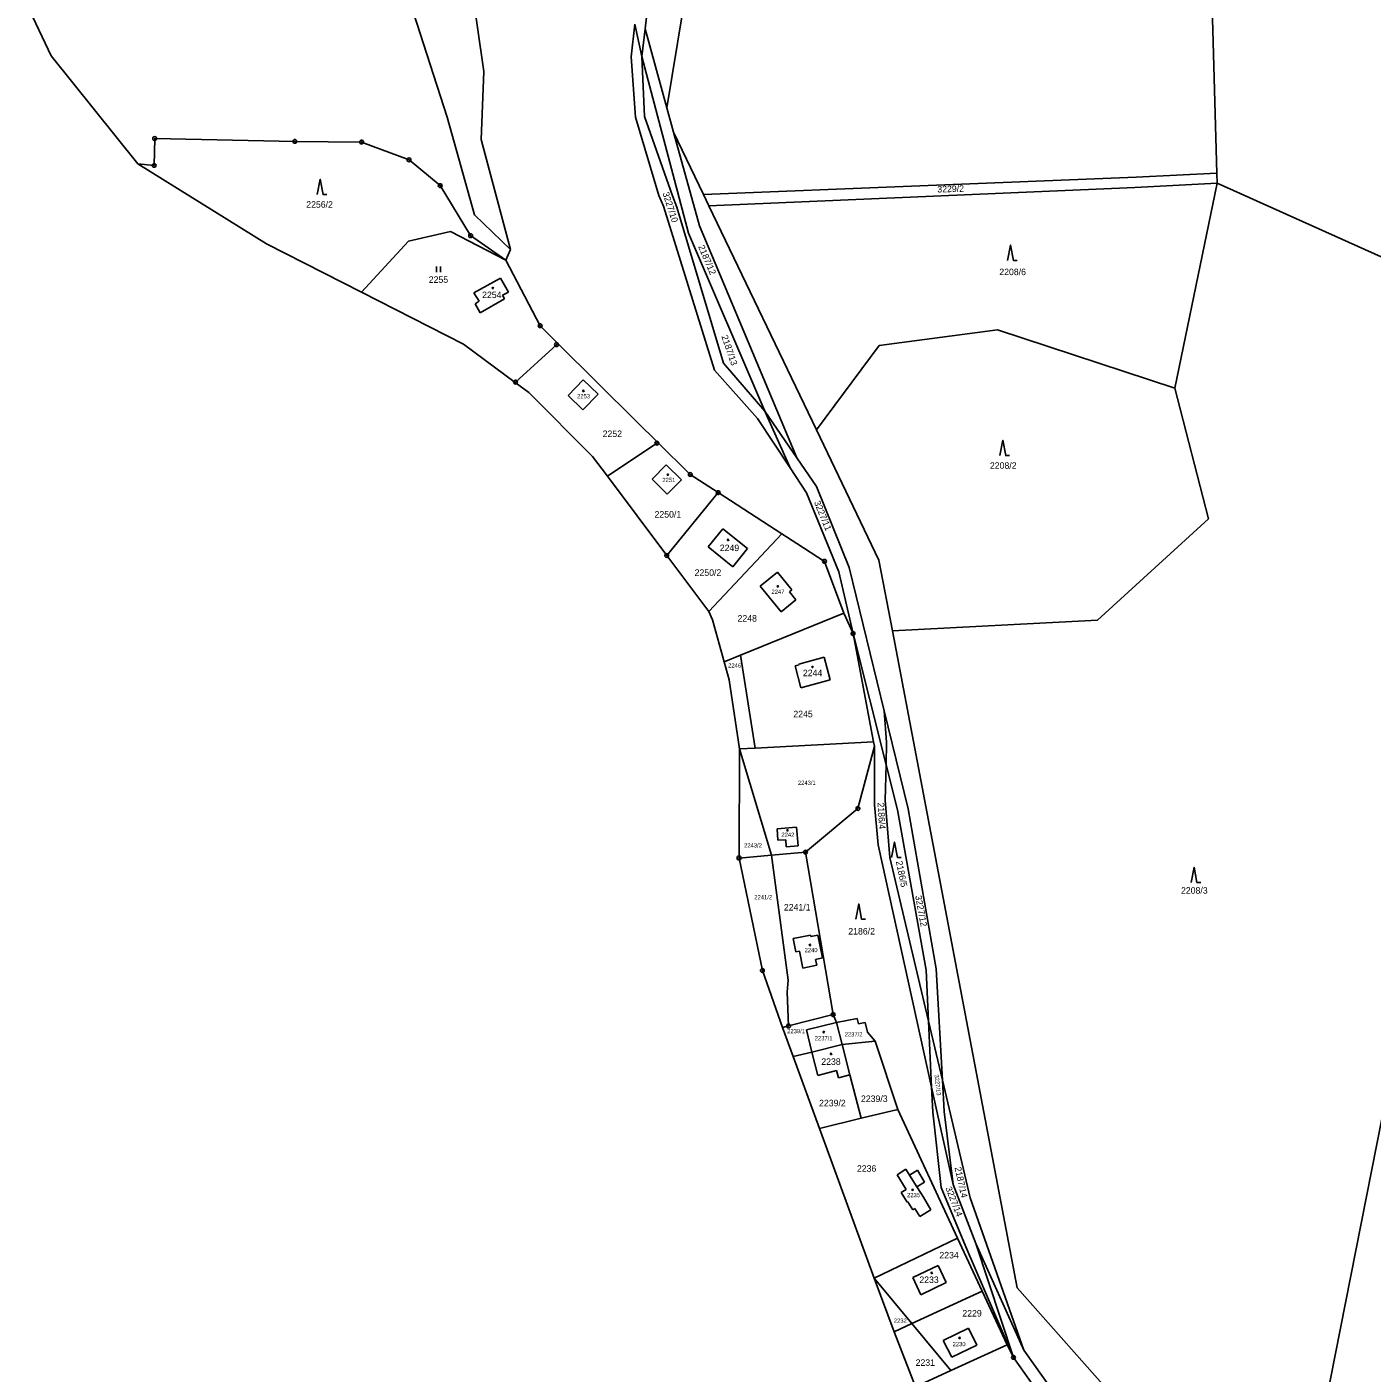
# Model space of a CAD drawing. Extents: x -736345 to -729997, y -1130177 to -1122501.
# Drawn here: x -734700.4 to -734349.4, y -1129772.2 to -1129421.1 of the extents above; entities that cross this region are included whole.
import ezdxf

# ---------------------------------------------------------------- set-up
doc = ezdxf.new("R2010")
doc.units = 0
for name, color, linetype in [('Vrstva 1', 7, 'Continuous'), ('Vrstva 13', 7, 'Continuous'), ('Vrstva 18', 7, 'Continuous'), ('Vrstva 19', 7, 'Continuous'), ('Vrstva 25', 7, 'Continuous'), ('Vrstva 4', 7, 'Continuous')]:
    doc.layers.add(name, color=color, linetype=linetype)

msp = doc.modelspace()

# ---------------------------------------------------------------- linework, layer by layer
at = {"layer": 'Vrstva 1'}
for points in [[(-734533.42, -1129442.26), (-734522.14, -1129373.62)], [(-734612.83, -1129376.15), (-734590.74, -1129444.65)], [(-734391.5, -1129403.36), (-734389.91, -1129459.3)], [(-734584.52, -1129409.15), (-734581.13, -1129432.75)], [(-734539.12, -1129421.6), (-734537.7, -1129409.35)], [(-734541.75, -1129420.42), (-734542.71, -1129428.92)], [(-734541.75, -1129420.42), (-734539.95, -1129428.83)], [(-734539.95, -1129428.83), (-734539.12, -1129421.6)], [(-734533.42, -1129442.26), (-734539.12, -1129421.6)], [(-734541.63, -1129444.65), (-734542.71, -1129428.92)], [(-734539.24, -1129444.51), (-734539.95, -1129428.83)], [(-734539.95, -1129428.83), (-734527.75, -1129474.96)], [(-734581.13, -1129432.75), (-734581.87, -1129450.52)], [(-734531.67, -1129448.59), (-734533.42, -1129442.26)], [(-734590.74, -1129444.65), (-734583.63, -1129470.11)], [(-734535.48, -1129465.07), (-734541.63, -1129444.65)], [(-734531.93, -1129465.17), (-734539.24, -1129444.51)], [(-734667.17, -1129457.25), (-734667.04, -1129450.26)], [(-734630.47, -1129451), (-734667.04, -1129450.26)], [(-734581.87, -1129450.52), (-734574.23, -1129479.22)], [(-734523.87, -1129464.85), (-734531.67, -1129448.59)], [(-734524.93, -1129473.03), (-734531.67, -1129448.59)], [(-734630.47, -1129451), (-734613.06, -1129451.16)], [(-734600.69, -1129455.81), (-734613.06, -1129451.16)], [(-734671.43, -1129456.81), (-734667.17, -1129457.25)], [(-734592.57, -1129462.53), (-734600.69, -1129455.81)], [(-734523.87, -1129464.85), (-734411.02, -1129460.3)], [(-734389.91, -1129459.3), (-734411.02, -1129460.3)], [(-734389.91, -1129459.3), (-734389.83, -1129461.93)], [(-734584.62, -1129475.58), (-734592.57, -1129462.53)], [(-734522.44, -1129467.82), (-734523.87, -1129464.85)], [(-734411.35, -1129462.99), (-734522.44, -1129467.82)], [(-734389.83, -1129461.93), (-734411.35, -1129462.99)], [(-734400.92, -1129515.32), (-734389.83, -1129461.93)], [(-734347.07, -1129481.06), (-734389.83, -1129461.93)], [(-734534.34, -1129467.87), (-734535.48, -1129465.07)], [(-734534.34, -1129467.87), (-734520.97, -1129510.65)], [(-734530.86, -1129468.19), (-734531.93, -1129465.17)], [(-734518.69, -1129508.85), (-734530.86, -1129468.19)], [(-734522.44, -1129467.82), (-734494.4, -1129526.24)], [(-734583.63, -1129470.11), (-734574.23, -1129479.22)], [(-734589.91, -1129474.48), (-734600.81, -1129477.05)], [(-734575.47, -1129481.98), (-734589.91, -1129474.48)], [(-734507.88, -1129521.35), (-734527.75, -1129474.96)], [(-734524.93, -1129473.03), (-734499.53, -1129533.55)], [(-734600.81, -1129477.05), (-734613.09, -1129490.3)], [(-734575.47, -1129481.98), (-734584.62, -1129475.58)], [(-734574.23, -1129479.22), (-734575.47, -1129481.98)], [(-734566.49, -1129499.07), (-734575.47, -1129481.98)], [(-734576.81, -1129486.63), (-734583.74, -1129490.47)], [(-734574.77, -1129490.31), (-734576.81, -1129486.63)], [(-734583.74, -1129490.47), (-734582.41, -1129492.69)], [(-734582.41, -1129492.69), (-734583.46, -1129493.32)], [(-734582.11, -1129495.68), (-734575.75, -1129492.05)], [(-734576.27, -1129491.14), (-734574.77, -1129490.31)], [(-734575.75, -1129492.05), (-734576.27, -1129491.14)], [(-734583.46, -1129493.32), (-734582.11, -1129495.68)], [(-734561.9, -1129503.74), (-734566.49, -1129499.07)], [(-734478.05, -1129504.24), (-734447.18, -1129500.1)], [(-734447.18, -1129500.1), (-734400.92, -1129515.32)], [(-734572.9, -1129513.77), (-734562.2, -1129504.01)], [(-734562.2, -1129504.01), (-734561.9, -1129503.74)], [(-734561.9, -1129503.74), (-734541.38, -1129524.04)], [(-734494.4, -1129526.24), (-734478.05, -1129504.24)], [(-734520.97, -1129510.65), (-734509.77, -1129523.24)], [(-734507.88, -1129521.35), (-734518.69, -1129508.85)], [(-734572.97, -1129513.84), (-734572.9, -1129513.77)], [(-734559.21, -1129517.26), (-734555.23, -1129513.14)], [(-734555.23, -1129513.14), (-734551.33, -1129516.91)], [(-734555.31, -1129521.03), (-734559.21, -1129517.26)], [(-734551.33, -1129516.91), (-734555.31, -1129521.03)], [(-734400.92, -1129515.32), (-734392.09, -1129549.47)], [(-734541.38, -1129524.04), (-734535.77, -1129529.55)], [(-734509.77, -1129523.24), (-734501.3, -1129536.1)], [(-734499.53, -1129533.55), (-734507.88, -1129521.35)], [(-734507.88, -1129521.35), (-734501.3, -1129536.1)], [(-734478.09, -1129560.23), (-734494.4, -1129526.24)], [(-734536.02, -1129529.71), (-734548.95, -1129538.34)], [(-734535.77, -1129529.55), (-734536.02, -1129529.71)], [(-734535.77, -1129529.55), (-734527.31, -1129537.87)], [(-734494.41, -1129541.04), (-734499.53, -1129533.55)], [(-734537.28, -1129539.05), (-734533.58, -1129535.32)], [(-734533.58, -1129535.32), (-734529.63, -1129539.24)], [(-734527.31, -1129537.87), (-734520.04, -1129542.59)], [(-734501.3, -1129536.1), (-734496.97, -1129542.68)], [(-734533.33, -1129542.97), (-734537.28, -1129539.05)], [(-734529.63, -1129539.24), (-734533.33, -1129542.97)], [(-734485.86, -1129562.13), (-734494.41, -1129541.04)], [(-734520.04, -1129542.59), (-734533.46, -1129558.99)], [(-734520.04, -1129542.59), (-734503.47, -1129553.35)], [(-734496.97, -1129542.68), (-734488.58, -1129563.27)], [(-734522.65, -1129556.76), (-734518.83, -1129552.03)], [(-734518.83, -1129552.03), (-734512.41, -1129557.21)], [(-734392.09, -1129549.47), (-734421.07, -1129575.85)], [(-734522.5, -1129573.6), (-734503.47, -1129553.35)], [(-734503.47, -1129553.35), (-734499.55, -1129555.9)], [(-734499.55, -1129555.9), (-734492.3, -1129560.52)], [(-734522.65, -1129556.76), (-734516.23, -1129561.94)], [(-734512.41, -1129557.21), (-734516.23, -1129561.94)], [(-734492.3, -1129560.52), (-734487.22, -1129574.06)], [(-734488.58, -1129563.27), (-734484.86, -1129579.37)], [(-734476.74, -1129599.5), (-734485.86, -1129562.13)], [(-734474.6, -1129578.6), (-734478.09, -1129560.23)], [(-734509.07, -1129566.98), (-734504.6, -1129563.35)], [(-734504.6, -1129563.35), (-734500.84, -1129567.95)], [(-734503.59, -1129573.7), (-734509.07, -1129566.98)], [(-734500.84, -1129567.95), (-734501.47, -1129568.46)], [(-734501.47, -1129568.46), (-734499.75, -1129570.57)], [(-734499.75, -1129570.57), (-734503.59, -1129573.7)], [(-734487.22, -1129574.06), (-734514.19, -1129585.02)], [(-734487.22, -1129574.06), (-734484.86, -1129579.37)], [(-734421.07, -1129575.85), (-734474.6, -1129578.6)], [(-734476.25, -1129613.58), (-734484.86, -1129579.37)], [(-734484.86, -1129579.37), (-734479.52, -1129607.57)], [(-734474.6, -1129578.6), (-734442, -1129750)], [(-734514.19, -1129585.02), (-734518.45, -1129586.75)], [(-734514.19, -1129585.02), (-734510.39, -1129609.22)], [(-734499.94, -1129587.76), (-734498.92, -1129587.5)], [(-734498.44, -1129593.52), (-734499.94, -1129587.76)], [(-734498.97, -1129587.3), (-734492.35, -1129585.54)], [(-734498.92, -1129587.5), (-734498.97, -1129587.3)], [(-734492.35, -1129585.54), (-734490.79, -1129591.44)], [(-734490.79, -1129591.44), (-734498.44, -1129593.52)], [(-734470.49, -1129625.11), (-734476.74, -1129599.5)], [(-734476.09, -1129607.64), (-734476.74, -1129599.5)], [(-734479.52, -1129607.57), (-734510.39, -1129609.22)], [(-734479.29, -1129608.68), (-734483.57, -1129624.97)], [(-734479.52, -1129607.57), (-734479.29, -1129608.68)], [(-734479.29, -1129608.68), (-734479.22, -1129624.06)], [(-734476.25, -1129613.58), (-734476.09, -1129607.64)], [(-734510.39, -1129609.22), (-734514.48, -1129609.44)], [(-734506.13, -1129637.15), (-734514.48, -1129609.44)], [(-734476.49, -1129622.79), (-734476.25, -1129613.58)], [(-734473.3, -1129625.29), (-734476.25, -1129613.58)], [(-734475.27, -1129637.79), (-734476.49, -1129622.79)], [(-734483.57, -1129624.97), (-734497.25, -1129636.38)], [(-734479.22, -1129624.06), (-734478.28, -1129634.46)], [(-734465.79, -1129667.18), (-734473.3, -1129625.29)], [(-734463.13, -1129666.77), (-734470.49, -1129625.11)], [(-734504.66, -1129630.28), (-734499.63, -1129629.84)], [(-734499.63, -1129629.84), (-734499.21, -1129634.71)], [(-734504.47, -1129633.28), (-734504.66, -1129630.28)], [(-734502.42, -1129633.13), (-734504.47, -1129633.28)], [(-734502.29, -1129634.94), (-734502.42, -1129633.13)], [(-734506.13, -1129637.15), (-734497.25, -1129636.38)], [(-734499.21, -1129634.71), (-734502.29, -1129634.94)], [(-734497.25, -1129636.38), (-734490.06, -1129678.74)], [(-734478.28, -1129634.46), (-734464.37, -1129697.63)], [(-734514.6, -1129637.89), (-734506.13, -1129637.15)], [(-734506.13, -1129637.15), (-734501.77, -1129669.78)], [(-734465.17, -1129680.47), (-734475.27, -1129637.79)], [(-734333.35, -1129637.24), (-734367.13, -1129808.5)], [(-734500.44, -1129658.9), (-734495.91, -1129657.99)], [(-734495.91, -1129657.99), (-734495.83, -1129658.36)], [(-734495.83, -1129658.36), (-734494.04, -1129658)], [(-734494.04, -1129658), (-734492.84, -1129663.96)], [(-734499.74, -1129662.35), (-734500.44, -1129658.9)], [(-734498.84, -1129662.17), (-734499.74, -1129662.35)], [(-734497.94, -1129666.6), (-734498.84, -1129662.17)], [(-734492.84, -1129663.96), (-734494.62, -1129664.32)], [(-734494.62, -1129664.32), (-734494.3, -1129665.87)], [(-734494.3, -1129665.87), (-734497.94, -1129666.6)], [(-734465.17, -1129680.47), (-734465.79, -1129667.18)], [(-734461.54, -1129695.79), (-734463.13, -1129666.77)], [(-734501.77, -1129669.78), (-734502.06, -1129672.85)], [(-734502.06, -1129672.85), (-734501.66, -1129681.7)], [(-734490.06, -1129678.74), (-734501.66, -1129681.7)], [(-734490.06, -1129678.74), (-734489.19, -1129680.8)], [(-734501.66, -1129681.7), (-734503.24, -1129682.08)], [(-734496.99, -1129682.7), (-734489.19, -1129680.8)], [(-734483.74, -1129679.76), (-734489.19, -1129680.8)], [(-734489.19, -1129680.8), (-734487.72, -1129686.56)], [(-734483.43, -1129681.17), (-734483.74, -1129679.76)], [(-734481.67, -1129680.78), (-734483.43, -1129681.17)], [(-734481.07, -1129683.32), (-734481.67, -1129680.78)], [(-734464.37, -1129697.63), (-734465.17, -1129680.47)], [(-734461.54, -1129695.79), (-734465.17, -1129680.47)], [(-734495.57, -1129688.49), (-734496.99, -1129682.7)], [(-734487.72, -1129686.56), (-734479.06, -1129685.69)], [(-734479.06, -1129685.69), (-734481.07, -1129683.32)], [(-734479.06, -1129685.69), (-734473.2, -1129703.49)], [(-734500.46, -1129689.68), (-734495.57, -1129688.49)], [(-734495.57, -1129688.49), (-734487.72, -1129686.56)], [(-734494.08, -1129694.62), (-734495.57, -1129688.49)], [(-734487.72, -1129686.56), (-734485.7, -1129694.48)], [(-734489.15, -1129693.32), (-734494.08, -1129694.62)], [(-734488.64, -1129695.25), (-734489.15, -1129693.32)], [(-734485.7, -1129694.48), (-734488.64, -1129695.25)], [(-734482.73, -1129705.78), (-734485.7, -1129694.48)], [(-734461.09, -1129704.04), (-734461.54, -1129695.79)], [(-734454.27, -1129726.51), (-734461.54, -1129695.79)], [(-734464.37, -1129697.63), (-734464.06, -1129704.17)], [(-734464.37, -1129697.63), (-734458.77, -1129723.04)], [(-734473.2, -1129703.49), (-734482.73, -1129705.78)], [(-734473.2, -1129703.49), (-734457.62, -1129737.04)], [(-734482.73, -1129705.78), (-734493.61, -1129708.4)], [(-734464.06, -1129704.17), (-734461.89, -1129723.85)], [(-734458.77, -1129723.04), (-734461.09, -1129704.04)], [(-734473.36, -1129720.52), (-734471.06, -1129719.08)], [(-734471, -1129724.33), (-734473.36, -1129720.52)], [(-734471.06, -1129719.08), (-734470.09, -1129720.58)], [(-734468.06, -1129719.34), (-734470.09, -1129720.58)], [(-734468.06, -1129719.34), (-734466.19, -1129722.4)], [(-734472.3, -1129725.14), (-734471, -1129724.33)], [(-734466.19, -1129722.4), (-734468.22, -1129723.64)], [(-734468.22, -1129723.64), (-734466.49, -1129726.36)], [(-734461.89, -1129723.85), (-734455.41, -1129739.28)], [(-734452.86, -1129738.39), (-734458.77, -1129723.04)], [(-734470.73, -1129727.67), (-734472.3, -1129725.14)], [(-734470.52, -1129727.54), (-734470.73, -1129727.67)], [(-734469.24, -1129729.61), (-734470.52, -1129727.54)], [(-734466.49, -1129726.36), (-734464.59, -1129729.68)], [(-734440.32, -1129766.22), (-734454.27, -1129726.51)], [(-734468.74, -1129729.3), (-734469.24, -1129729.61)], [(-734467.45, -1129731.4), (-734468.74, -1129729.3)], [(-734464.59, -1129729.68), (-734467.45, -1129731.4)], [(-734457.62, -1129737.04), (-734479.31, -1129747.47)], [(-734457.62, -1129737.04), (-734451.15, -1129750.87)], [(-734440.32, -1129766.22), (-734452.86, -1129738.39)], [(-734443.01, -1129768.14), (-734452.86, -1129738.39)], [(-734455.41, -1129739.28), (-734443.01, -1129768.14)], [(-734469.3, -1129747.34), (-734462.68, -1129744.17)], [(-734462.68, -1129744.17), (-734460.54, -1129748.63)], [(-734469.49, -1129759.33), (-734479.31, -1129747.47)], [(-734467.16, -1129751.8), (-734469.3, -1129747.34)], [(-734460.54, -1129748.63), (-734467.16, -1129751.8)], [(-734469.49, -1129759.33), (-734451.15, -1129750.87)], [(-734451.15, -1129750.87), (-734444.66, -1129764.85)], [(-734442, -1129750), (-734389.31, -1129809.44)], [(-734474.15, -1129761.48), (-734469.49, -1129759.33)], [(-734469.49, -1129759.33), (-734459.37, -1129771.56)], [(-734461.31, -1129763.69), (-734454.71, -1129760.48)], [(-734454.71, -1129760.48), (-734452.55, -1129764.92)], [(-734459.11, -1129768.06), (-734461.31, -1129763.69)], [(-734444.66, -1129764.85), (-734459.37, -1129771.56)], [(-734452.55, -1129764.92), (-734459.11, -1129768.06)], [(-734443.01, -1129768.14), (-734444.66, -1129764.85)], [(-734432.84, -1129776.73), (-734440.32, -1129766.22)], [(-734443.01, -1129768.14), (-734435.57, -1129778.59)], [(-734459.37, -1129771.56), (-734468.6, -1129775.77)]]:
    msp.add_lwpolyline(points, dxfattribs=at)
at = {"layer": 'Vrstva 13'}
for points in [[(-734700.37, -1129415.29), (-734694.01, -1129428.71)], [(-734694.01, -1129428.71), (-734671.43, -1129456.81)], [(-734671.43, -1129456.81), (-734637.84, -1129477.74)], [(-734613.09, -1129490.3), (-734637.84, -1129477.74)], [(-734613.09, -1129490.3), (-734586.51, -1129503.85)], [(-734586.51, -1129503.85), (-734572.97, -1129513.84)], [(-734572.97, -1129513.84), (-734569.43, -1129516.46)], [(-734552.8, -1129533.21), (-734569.43, -1129516.46)], [(-734548.95, -1129538.34), (-734552.8, -1129533.21)], [(-734548.95, -1129538.34), (-734533.46, -1129558.99)], [(-734533.46, -1129558.99), (-734522.5, -1129573.6)], [(-734521.51, -1129575.8), (-734522.5, -1129573.6)], [(-734518.45, -1129586.75), (-734521.51, -1129575.8)], [(-734517.15, -1129591.4), (-734518.45, -1129586.75)], [(-734514.48, -1129609.44), (-734517.15, -1129591.4)], [(-734514.6, -1129637.89), (-734514.48, -1129609.44)], [(-734508.51, -1129667.22), (-734514.6, -1129637.89)], [(-734503.24, -1129682.08), (-734508.51, -1129667.22)], [(-734500.46, -1129689.68), (-734503.24, -1129682.08)], [(-734493.61, -1129708.4), (-734500.46, -1129689.68)], [(-734479.31, -1129747.47), (-734493.61, -1129708.4)], [(-734479.31, -1129747.47), (-734474.15, -1129761.48)], [(-734468.6, -1129775.77), (-734474.15, -1129761.48)]]:
    msp.add_lwpolyline(points, dxfattribs=at)
at = {"layer": 'Vrstva 25'}
for points in [[(-734624.61, -1129464.88), (-734623.86, -1129460.88), (-734623.11, -1129464.88), (-734622.11, -1129464.88)], [(-734444.52, -1129482.04), (-734443.77, -1129478.04), (-734443.02, -1129482.04), (-734442.02, -1129482.04)], [(-734593.537, -1129485.125), (-734593.537, -1129483.625)], [(-734592.503, -1129485.125), (-734592.503, -1129483.625)], [(-734446.52, -1129532.92), (-734445.77, -1129528.92), (-734445.02, -1129532.92), (-734444.02, -1129532.92)], [(-734474.79, -1129637.75), (-734474.04, -1129633.75), (-734473.29, -1129637.75), (-734472.29, -1129637.75)], [(-734396.65, -1129644.29), (-734395.9, -1129640.29), (-734395.15, -1129644.29), (-734394.15, -1129644.29)], [(-734484.12, -1129653.88), (-734483.37, -1129649.88), (-734482.62, -1129653.88), (-734481.62, -1129653.88)]]:
    msp.add_lwpolyline(points, dxfattribs=at)
for centre, radius in [((-734667.04, -1129450.26), 0.5), ((-734667.04, -1129450.26), 0.032), ((-734630.47, -1129451), 0.5), ((-734630.47, -1129451), 0.032), ((-734613.06, -1129451.16), 0.5), ((-734613.06, -1129451.16), 0.032), ((-734667.17, -1129457.25), 0.5), ((-734667.17, -1129457.25), 0.032), ((-734600.69, -1129455.81), 0.5), ((-734600.69, -1129455.81), 0.032), ((-734592.57, -1129462.53), 0.5), ((-734592.57, -1129462.53), 0.032), ((-734584.62, -1129475.58), 0.5), ((-734584.62, -1129475.58), 0.032), ((-734578.83, -1129489.24), 0.175), ((-734566.49, -1129499.07), 0.5), ((-734566.49, -1129499.07), 0.032), ((-734562.2, -1129504.01), 0.5), ((-734562.2, -1129504.01), 0.032), ((-734572.9, -1129513.77), 0.5), ((-734572.9, -1129513.77), 0.032), ((-734555.19, -1129516.06), 0.175), ((-734536.02, -1129529.71), 0.5), ((-734536.02, -1129529.71), 0.032), ((-734533.17, -1129537.95), 0.175), ((-734527.31, -1129537.87), 0.5), ((-734527.31, -1129537.87), 0.032), ((-734520.04, -1129542.59), 0.5), ((-734520.04, -1129542.59), 0.032), ((-734517.44, -1129554.92), 0.175), ((-734533.46, -1129558.99), 0.5), ((-734533.46, -1129558.99), 0.032), ((-734492.3, -1129560.52), 0.5), ((-734492.3, -1129560.52), 0.032), ((-734504.47, -1129567.07), 0.175), ((-734484.86, -1129579.37), 0.5), ((-734484.86, -1129579.37), 0.032), ((-734495.43, -1129588.08), 0.175), ((-734483.57, -1129624.97), 0.5), ((-734483.57, -1129624.97), 0.032), ((-734501.95, -1129630.64), 0.175), ((-734497.25, -1129636.38), 0.5), ((-734497.25, -1129636.38), 0.032), ((-734514.6, -1129637.89), 0.5), ((-734514.6, -1129637.89), 0.032), ((-734496.11, -1129660.58), 0.175), ((-734508.51, -1129667.22), 0.5), ((-734508.51, -1129667.22), 0.032), ((-734490.06, -1129678.74), 0.5), ((-734490.06, -1129678.74), 0.032), ((-734501.66, -1129681.7), 0.5), ((-734501.66, -1129681.7), 0.032), ((-734492.5, -1129683.3), 0.175), ((-734490.57, -1129688.98), 0.175), ((-734469.33, -1129724.43), 0.175), ((-734464.31, -1129746.11), 0.175), ((-734457.05, -1129763.06), 0.175), ((-734443.01, -1129768.14), 0.5), ((-734443.01, -1129768.14), 0.032)]:
    msp.add_circle(centre, radius, dxfattribs=at)
at = {"layer": 'Vrstva 4'}
msp.add_lwpolyline([(-734470.09, -1129720.58), (-734468.22, -1129723.64)], dxfattribs=at)

# ---------------------------------------------------------------- texts
at = {"layer": 'Vrstva 18'}
for s, height, rotation, p in [('3227/10', 1.7, 288.10229, (-734534.578, -1129464.507)), ('3229/2', 1.7, 1.70001, (-734462.837, -1129464.335)), ('2187/12', 1.7, 293.10233, (-734525.298, -1129478.425)), ('2187/13', 1.7, 289.0023, (-734519.226, -1129501.853)), ('3227/11', 1.7, 292.30233, (-734495.07, -1129545.129)), ('2186/4', 1.7, 273.30218, (-734478.459, -1129623.478)), ('2186/5', 1.7, 281.30224, (-734473.675, -1129638.806)), ('3227/12', 1.7, 280.50223, (-734468.657, -1129647.81)), ('3227/13', 1.1, 276.5022, (-734463.609, -1129694.416)), ('2187/14', 1.7, 282.50225, (-734458.372, -1129718.641)), ('3227/14', 1.7, 291.60232, (-734460.791, -1129723.972))]:
    msp.add_text(s, height=height, rotation=rotation, dxfattribs=at).set_placement(p)
for s, height, p in [('2256/2', 1.7, (-734627.5, -1129468.29)), ('2208/6', 1.7, (-734446.7, -1129485.88)), ('2255', 1.7, (-734595.54, -1129487.89)), ('2252', 1.7, (-734550.18, -1129528.1)), ('2208/2', 1.7, (-734449.15, -1129536.39)), ('2250/1', 1.7, (-734536.64, -1129549.11)), ('2250/2', 1.7, (-734526.18, -1129564.31)), ('2248', 1.7, (-734514.99, -1129576.24)), ('2246', 1.1, (-734517.44, -1129588.22)), ('2245', 1.7, (-734500.43, -1129601.19)), ('2243/1', 1.1, (-734499.23, -1129618.81)), ('2243/2', 1.1, (-734513.28, -1129635.15)), ('2241/2', 1.1, (-734510.61, -1129648.66)), ('2208/3', 1.7, (-734399.3, -1129647.2)), ('2241/1', 1.7, (-734502.9, -1129651.59)), ('2186/2', 1.7, (-734486.09, -1129657.85)), ('2239/1', 1.1, (-734502.03, -1129683.58)), ('2237/2', 1.1, (-734487.03, -1129684.43)), ('2239/3', 1.7, (-734482.79, -1129701.53)), ('2239/2', 1.7, (-734493.72, -1129702.65)), ('2236', 1.7, (-734483.84, -1129719.72)), ('2234', 1.7, (-734462.33, -1129742.32)), ('2229', 1.7, (-734456.34, -1129757.48)), ('2232', 1.1, (-734474.21, -1129759.1)), ('2231', 1.7, (-734468.53, -1129770.34))]:
    msp.add_text(s, height=height, dxfattribs=at).set_placement(p)
at = {"layer": 'Vrstva 19'}
for s, height, p in [('2254', 1.7, (-734581.62, -1129491.86)), ('2253', 1.1, (-734556.84, -1129518)), ('2251', 1.1, (-734534.6, -1129539.84)), ('2249', 1.7, (-734519.62, -1129557.85)), ('2247', 1.1, (-734506.13, -1129569)), ('2244', 1.7, (-734497.94, -1129590.47)), ('2242', 1.1, (-734503.54, -1129632.36)), ('2240', 1.1, (-734497.5, -1129662.45)), ('2237/1', 1.1, (-734494.85, -1129685.44)), ('2238', 1.7, (-734493.14, -1129691.84)), ('2235', 1.1, (-734470.75, -1129726.35)), ('2233', 1.7, (-734467.56, -1129748.74)), ('2230', 1.1, (-734458.88, -1129765.21))]:
    msp.add_text(s, height=height, dxfattribs=at).set_placement(p)

doc.saveas('drawing.dxf')
